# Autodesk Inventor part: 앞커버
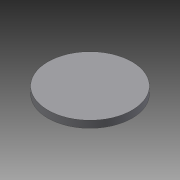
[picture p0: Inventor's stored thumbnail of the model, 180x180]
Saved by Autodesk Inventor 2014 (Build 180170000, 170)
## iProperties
Created: 2024-02
Part Number: 앞커버
Material: 알루미늄 6061
Document SubType Name: Modeling
Designer: mdu-01
Density: 2.71 g/cm^3
Mass: 306.094 g
Surface Area: 299.031 cm^2
Volume: 112.95 cm^3
Appearance: 기본값(1)
Author: mdu-01
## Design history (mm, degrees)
sketch "스케치1"
  geometry: C1 r 60 at (0, 0) reference; C2 r 46 at (0, 0) reference; C3 r 15 at (0, 0) reference; C4 r 11 at (0, -31) reference; A1 r 41 centre (0, 0) between (20.39, -35.57) and (-20.39, -35.57); A2 r 20 centre (0, 0) between (12.218, -15.835) and (-12.218, -15.835); A3 r 16 centre (0, -31) between (-11.832, -20.229) and (-15.914, -32.657); A4 r 16 centre (0, -31) between (15.914, -32.657) and (11.832, -20.229); A5 r 3 centre (-14.05, -18.21) between (-11.832, -20.229) and (-12.218, -15.835); A6 r 3 centre (14.05, -18.21) between (12.218, -15.835) and (11.832, -20.229); A7 r 3 centre (18.898, -32.968) between (15.914, -32.657) and (20.39, -35.57); A8 r 3 centre (-18.898, -32.968) between (-20.39, -35.57) and (-15.914, -32.657); 1 further point
  constraints: 16 point on circle, 8 centre point, 8 tangent, 4 equal radius
  dimensions: "d0" = 5 radial gap between concentric circles of C2 A1; "d1" = 5 radial gap between concentric circles of A2 C3; "d3" = 5 radial gap between concentric circles of A4 C4; "d4" = 3 radius of A5
  node "참조1"
  node "참조2"
  node "참조3"
  node "참조4"
extrude "돌출1" new body sketch "스케치1" distance "d5" = 10; taper "d6" = 0 deg
extrude "돌출2" join sketch "스케치1" distance "d7" = 3; taper "d8" = 0 deg
sketch "스케치2"
  geometry: C1 r 20 at (0, 0); 1 further point
  constraints: 1 centre point, 1 coincident
  dimensions: "d9" = 40 diameter of C1
extrude "돌출3" join sketch "스케치2" distance "d10" = 7; taper "d11" = 0 deg
fillet "모깎기1" dims "d12" = 3
chamfer "모따기1" distance "d13" = 1; stored, may be unused: second distance "d14" = 2, angle "d15" = 45 deg
sketch "스케치3"
  geometry: C1 r 1.621 at (0, 52) reference; 1 further point
hole "구멍1" sketch "스케치3" at (0, 52) diameter "d16" = 4.5; stored, may be unused: countersink angle "d20" = 90 deg, drill point angle "d22" = 118 deg; dims "d17" = 6, "d18" = 8, "d19" = 4.4, "d21" = 8
sketch "스케치4"
  geometry: L1 (15, 3.7)-(15, -2.7) reference; L2 (-14.7, 4)-(14.7, 4) reference; L3 (14.7, -3)-(-14.7, -3) reference; L4 (14.7, 4)-(13, 4); L5 (-17, 17)-(17, 17) reference; L6 (15, 16.2)-(15, 9); L7 (14.7, 8.7)-(13, 8.7); L8 (13, 8.7)-(13, 4); L9 (0, 17)-(0, -3); L10 (15.462, 17)-(15, 16.2); L11 (14.7, -3)-(15, -3); L12 (15, -3)-(15, -2.7); A1 r 0.3 centre (14.7, 3.7) between (15, 3.7) and (14.7, 4); A2 r 0.3 centre (14.7, 9) between (14.7, 8.7) and (15, 9); 1 further point
  constraints: 18 end point, 4 point on circle, 3 perpendicular, 3 tangent, 2 centre point, 2 midpoint, 2 point on line, 1 collinear, 1 parallel, 1 vertical, 2 other
  dimensions: "d26" = 2 distance from line of L4.end L1; "d28" = 0.3 radius of A2; "d29" = 30 diameter of L6 L9; "d30" = 8.3 distance between parallel lines of L7 L5; "d31" = 0.8 distance from line of L6.start L5; "d32" = 30 deg angle of L6 L10
revolve "회전1" sketch "스케치4" stored, may be unused: angle "d33" = 90 deg
sketch "스케치5"
  geometry: L1 (-20, 3.7)-(-20, -2.7) reference; L2 (-20.3, -3)-(-41.7, -3) reference; L3 (-41.7, 4)-(-20.3, 4) reference; L4 (-20.3, 4)-(-22, 4); L5 (-20, -2.7)-(-20, -3); L6 (-20, -3)-(-20.3, -3); L7 (-31, -3)-(-31, 7); L8 (-31, 7)-(-25, 7); A1 r 0.3 centre (-20.3, 3.7) between (-20, 3.7) and (-20.3, 4); A2 r 3 centre (-25, 4) between (-22, 4) and (-25, 7); 1 further point
  constraints: 12 end point, 4 perpendicular, 4 point on circle, 2 centre point, 2 point on line, 2 tangent, 1 midpoint, 1 vertical, 2 other
  dimensions: "d34" = 3 distance between parallel lines of L8 L3; "d35" = 2 distance from line of L4.end L1
revolve "회전2" sketch "스케치5" stored, may be unused: angle "d36" = 90 deg
chamfer "모따기2" distance "d37" = 1; stored, may be unused: second distance "d38" = 2, angle "d39" = 45 deg
node "솔리드1"
pattern_circular "원형 패턴1" dims angle "d24" = 360 deg
node "참조5"
node "참조6"
node "참조7"
node "참조8"
node "참조9"
other parameters: "d2" = 5
